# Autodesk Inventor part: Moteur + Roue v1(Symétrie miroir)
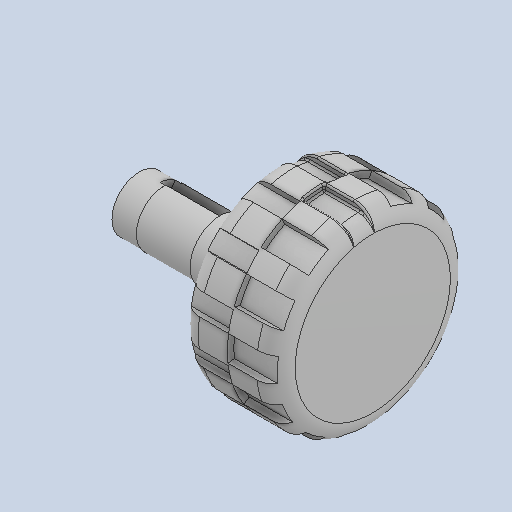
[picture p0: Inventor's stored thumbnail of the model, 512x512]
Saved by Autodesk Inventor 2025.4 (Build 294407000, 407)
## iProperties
Created: 2026-06
Part Number: Moteur + Roue v1(Symétrie miroir)
Material: Generic
Document SubType Name: Modeling
Designer: AdminForWorker
Density: 1 g/cm^3
Appearance: Default
Title: Moteur + Roue v1(Symétrie miroir)
Author: AdminForWorker
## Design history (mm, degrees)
feature "Body1"
feature "Roue" [Body]
body "Solid1"
body "Solid2"
